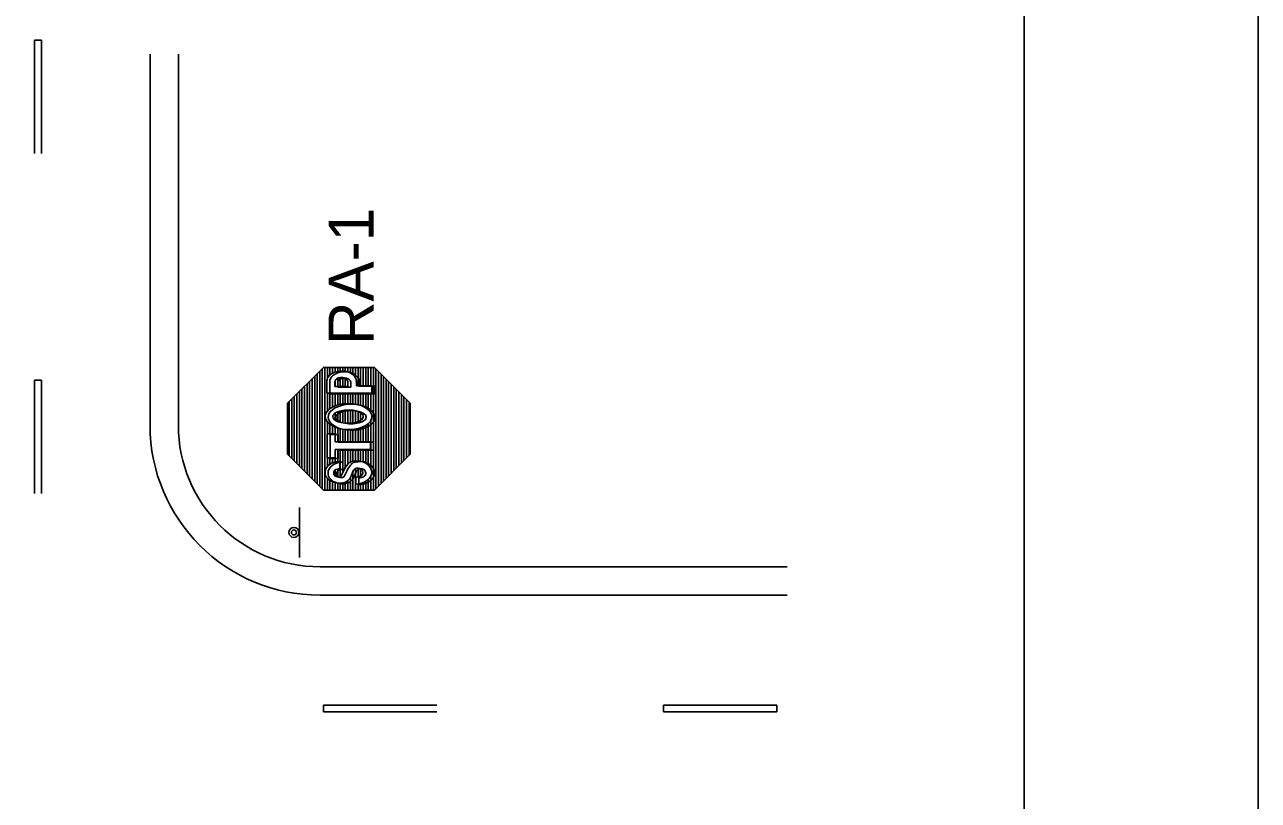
# Model space of a CAD drawing. Extents: x 1806 to 2022, y 110 to 389.
# Drawn here: x 1968.9 to 2021.6, y 280.3 to 313.4 of the extents above; entities that cross this region are included whole.
import ezdxf

# ---------------------------------------------------------------- set-up
doc = ezdxf.new("R2010")
doc.units = 0
for name, color, linetype in [('Level 10', 7, 'Continuous'), ('Level 2', 7, 'Continuous'), ('Level 44', 7, 'Continuous'), ('Level 50', 7, 'Continuous'), ('Level 60', 7, 'Continuous')]:
    doc.layers.add(name, color=color, linetype=linetype)

msp = doc.modelspace()

# ---------------------------------------------------------------- linework, layer by layer
at = {"layer": 'Level 10'}
for p, q in [((1974.267, 296.293), (1974.267, 312.134)), ((1975.477, 296.293), (1975.477, 312.134)), ((1981.525, 290.244), (2001.468, 290.244)), ((1981.525, 289.035), (2001.468, 289.035))]:
    msp.add_line(p, q, dxfattribs=at)
for radius in [7.258, 6.048]:
    msp.add_arc((1981.525, 296.293), radius, 180, 270, dxfattribs=at)
at = {"layer": 'Level 2'}
for p, q in [((1969.337, 312.722), (1969.337, 307.884)), ((1969.627, 312.722), (1969.337, 312.722)), ((1969.627, 307.884), (1969.627, 312.722)), ((1969.337, 298.208), (1969.337, 293.37)), ((1969.627, 298.208), (1969.337, 298.208)), ((1969.627, 293.37), (1969.627, 298.208)), ((1986.519, 284.342), (1981.681, 284.342)), ((1981.681, 284.342), (1981.681, 284.052)), ((1981.681, 284.052), (1986.519, 284.052)), ((2001.033, 284.342), (1996.195, 284.342)), ((1996.195, 284.342), (1996.195, 284.052)), ((1996.195, 284.052), (2001.033, 284.052)), ((2001.033, 284.052), (2001.033, 284.342))]:
    msp.add_line(p, q, dxfattribs=at)
at = {"layer": 'Level 44'}
for p, q in [((1981.668, 298.759), (1980.139, 297.23)), ((1983.845, 298.759), (1981.668, 298.759)), ((1985.375, 297.23), (1983.845, 298.759)), ((1981.815, 298.196), (1981.815, 297.662)), ((1981.943, 297.633), (1981.943, 298.169)), ((1982.16, 298.148), (1982.16, 297.939)), ((1982.16, 298.148), (1982.16, 297.939)), ((1982.718, 297.939), (1982.718, 298.144)), ((1982.718, 297.939), (1982.718, 298.144)), ((1983.078, 297.979), (1983.078, 298.179)), ((1983.201, 298.142), (1983.206, 297.951)), ((1983.206, 297.951), (1983.206, 298.151)), ((1981.815, 297.662), (1983.732, 297.662)), ((1983.859, 297.633), (1981.943, 297.633)), ((1982.16, 297.939), (1982.718, 297.939)), ((1982.16, 297.939), (1982.718, 297.939)), ((1982.287, 298.121), (1982.287, 297.913)), ((1982.287, 298.121), (1982.287, 297.913)), ((1982.287, 297.913), (1982.844, 297.913)), ((1982.287, 297.913), (1982.844, 297.913)), ((1982.844, 297.913), (1982.844, 298.117)), ((1982.844, 297.913), (1982.844, 298.117)), ((1983.732, 297.979), (1983.078, 297.979)), ((1983.206, 297.951), (1983.859, 297.951)), ((1983.732, 297.662), (1983.732, 297.979)), ((1983.859, 297.951), (1983.859, 297.633)), ((1980.139, 297.23), (1980.139, 295.052)), ((1985.375, 295.052), (1985.375, 297.23)), ((1981.876, 296.615), (1981.875, 296.625)), ((1982.202, 296.602), (1982.199, 296.615)), ((1982.177, 295.923), (1981.833, 295.923)), ((1981.833, 295.923), (1981.833, 294.904)), ((1981.961, 294.877), (1981.961, 295.897)), ((1981.961, 295.897), (1982.304, 295.897)), ((1982.177, 295.588), (1982.177, 295.923)), ((1983.676, 295.588), (1982.177, 295.588)), ((1982.304, 295.897), (1982.304, 295.561)), ((1982.304, 295.561), (1983.803, 295.561)), ((1983.676, 295.257), (1983.676, 295.588)), ((1983.803, 295.561), (1983.803, 295.229)), ((1980.139, 295.052), (1981.668, 293.523)), ((1982.168, 294.904), (1982.168, 295.257)), ((1982.168, 295.257), (1983.676, 295.257)), ((1983.803, 295.229), (1982.296, 295.229)), ((1982.296, 295.229), (1982.296, 294.877)), ((1983.845, 293.523), (1985.375, 295.052)), ((1981.833, 294.904), (1982.168, 294.904)), ((1982.296, 294.877), (1981.961, 294.877)), ((1982.369, 294.747), (1982.369, 294.421)), ((1982.496, 294.721), (1982.496, 294.393)), ((1983.057, 293.776), (1983.057, 294.076)), ((1983.184, 293.75), (1983.184, 294.05)), ((1981.668, 293.523), (1983.845, 293.523)), ((1983.563, 293.845), (1983.562, 293.843)), ((1980.65, 290.642), (1980.65, 292.775))]:
    msp.add_line(p, q, dxfattribs=at)
msp.add_lwpolyline([(1983.846, 298.759), (1985.375, 297.23), (1985.375, 295.052), (1983.846, 293.523), (1981.668, 293.523), (1980.14, 295.052), (1980.14, 297.23), (1981.668, 298.759)], close=True, dxfattribs=at)
for points in [[(1981.624, 293.567), (1981.624, 298.714)], [(1981.734, 293.523), (1981.734, 298.759)], [(1981.843, 298.295), (1981.843, 298.759)], [(1981.951, 298.436), (1981.951, 298.759)], [(1982.06, 298.505), (1982.06, 298.759)], [(1982.168, 298.557), (1982.168, 298.759)], [(1982.279, 298.583), (1982.279, 298.759)], [(1982.387, 298.598), (1982.387, 298.759)], [(1982.496, 298.601), (1982.496, 298.759)], [(1982.604, 298.587), (1982.604, 298.759)], [(1982.713, 298.557), (1982.713, 298.759)], [(1982.823, 298.519), (1982.823, 298.759)], [(1982.931, 298.445), (1982.931, 298.759)], [(1983.039, 298.295), (1983.039, 298.759)], [(1983.149, 297.979), (1983.149, 298.759)], [(1983.257, 297.979), (1983.257, 298.759)], [(1983.366, 297.979), (1983.366, 298.759)], [(1983.476, 297.979), (1983.476, 298.759)], [(1983.584, 297.979), (1983.584, 298.759)], [(1983.693, 297.979), (1983.693, 298.759)], [(1983.802, 293.523), (1983.802, 298.759)], [(1983.91, 293.589), (1983.91, 298.693)], [(1981.08, 294.111), (1981.08, 298.171)], [(1981.189, 294.003), (1981.189, 298.279)], [(1981.298, 293.894), (1981.298, 298.388)], [(1981.407, 293.785), (1981.407, 298.497)], [(1981.516, 293.677), (1981.516, 298.605)], [(1982.168, 297.939), (1982.168, 298.192)], [(1982.279, 297.939), (1982.279, 298.295)], [(1982.387, 297.939), (1982.387, 298.323)], [(1982.496, 297.934), (1982.496, 298.327)], [(1982.604, 297.939), (1982.604, 298.292)], [(1984.02, 293.698), (1984.02, 298.583)], [(1984.129, 293.806), (1984.129, 298.475)], [(1984.237, 293.915), (1984.237, 298.367)], [(1984.346, 294.025), (1984.346, 298.257)], [(1984.455, 294.134), (1984.455, 298.148)], [(1980.537, 294.656), (1980.537, 297.626)], [(1980.645, 294.548), (1980.645, 297.73)], [(1980.753, 294.439), (1980.753, 297.843)], [(1980.863, 294.331), (1980.863, 297.952)], [(1980.971, 294.22), (1980.971, 298.061)], [(1981.843, 296.889), (1981.843, 297.662)], [(1981.951, 296.995), (1981.951, 297.662)], [(1982.06, 297.064), (1982.06, 297.662)], [(1982.168, 297.111), (1982.168, 297.662)], [(1982.279, 297.151), (1982.279, 297.662)], [(1982.387, 297.178), (1982.387, 297.662)], [(1982.496, 297.199), (1982.496, 297.662)], [(1982.604, 297.208), (1982.604, 297.662)], [(1982.713, 297.217), (1982.713, 297.662)], [(1982.823, 297.212), (1982.823, 297.662)], [(1982.931, 297.205), (1982.931, 297.662)], [(1983.039, 297.187), (1983.039, 297.662)], [(1983.149, 297.165), (1983.149, 297.662)], [(1983.257, 297.133), (1983.257, 297.662)], [(1983.366, 297.089), (1983.366, 297.662)], [(1983.476, 297.033), (1983.476, 297.662)], [(1983.584, 296.955), (1983.584, 297.662)], [(1983.693, 296.824), (1983.693, 297.662)], [(1984.563, 294.242), (1984.563, 298.04)], [(1984.673, 294.351), (1984.673, 297.931)], [(1984.782, 294.461), (1984.782, 297.821)], [(1984.89, 294.569), (1984.89, 297.712)], [(1984.999, 294.677), (1984.999, 297.604)], [(1980.209, 294.983), (1980.209, 297.298)], [(1980.318, 294.873), (1980.318, 297.404)], [(1980.427, 294.764), (1980.427, 297.518)], [(1985.108, 294.787), (1985.108, 297.495)], [(1985.217, 294.901), (1985.217, 297.387)], [(1985.327, 295.004), (1985.327, 297.278)], [(1982.168, 296.503), (1982.168, 296.806)], [(1982.279, 296.45), (1982.279, 296.859)], [(1982.387, 296.42), (1982.387, 296.895)], [(1982.496, 296.39), (1982.496, 296.92)], [(1982.604, 296.384), (1982.604, 296.937)], [(1982.713, 296.377), (1982.713, 296.937)], [(1982.823, 296.377), (1982.823, 296.942)], [(1982.931, 296.39), (1982.931, 296.929)], [(1983.039, 296.411), (1983.039, 296.906)], [(1983.149, 296.445), (1983.149, 296.877)], [(1983.257, 296.494), (1983.257, 296.819)], [(1981.843, 295.923), (1981.843, 296.428)], [(1981.951, 295.923), (1981.951, 296.329)], [(1982.06, 295.923), (1982.06, 296.254)], [(1982.168, 295.923), (1982.168, 296.207)], [(1982.279, 295.588), (1982.279, 296.168)], [(1982.387, 295.588), (1982.387, 296.141)], [(1982.496, 295.588), (1982.496, 296.122)], [(1982.604, 295.592), (1982.604, 296.11)], [(1982.713, 295.588), (1982.713, 296.105)], [(1982.823, 295.588), (1982.823, 296.105)], [(1982.931, 295.588), (1982.931, 296.114)], [(1983.039, 295.588), (1983.039, 296.128)], [(1983.149, 295.588), (1983.149, 296.145)], [(1983.257, 295.588), (1983.257, 296.176)], [(1983.366, 295.588), (1983.366, 296.215)], [(1983.476, 295.588), (1983.476, 296.272)], [(1983.584, 295.588), (1983.584, 296.35)], [(1983.693, 294.447), (1983.693, 296.481)], [(1982.279, 294.742), (1982.279, 295.257)], [(1982.387, 294.103), (1982.387, 295.257)], [(1982.496, 294.242), (1982.496, 295.257)], [(1982.604, 294.487), (1982.604, 295.257)], [(1982.713, 294.634), (1982.713, 295.257)], [(1982.823, 294.717), (1982.823, 295.257)], [(1982.931, 294.747), (1982.931, 295.257)], [(1983.039, 294.764), (1983.039, 295.257)], [(1983.149, 294.764), (1983.149, 295.257)], [(1983.257, 294.757), (1983.257, 295.257)], [(1983.366, 294.722), (1983.366, 295.257)], [(1983.476, 294.669), (1983.476, 295.257)], [(1983.584, 294.591), (1983.584, 295.257)], [(1981.843, 294.53), (1981.843, 294.904)], [(1981.951, 294.626), (1981.951, 294.904)], [(1982.06, 294.686), (1982.06, 294.904)], [(1982.168, 294.717), (1982.168, 294.904)], [(1983.039, 293.523), (1983.039, 294.443)], [(1983.149, 294.086), (1983.149, 294.455)], [(1981.843, 293.523), (1981.843, 294.028)], [(1981.951, 293.523), (1981.951, 293.937)], [(1982.168, 294.134), (1982.168, 294.379)], [(1982.279, 294.086), (1982.279, 294.425)], [(1982.713, 293.523), (1982.713, 293.932)], [(1982.823, 293.523), (1982.823, 294.073)], [(1982.931, 293.523), (1982.931, 294.331)], [(1983.257, 294.119), (1983.257, 294.43)], [(1983.584, 293.523), (1983.584, 293.986)], [(1983.693, 293.523), (1983.693, 294.111)], [(1982.06, 293.523), (1982.06, 293.877)], [(1982.168, 293.523), (1982.168, 293.846)], [(1982.279, 293.523), (1982.279, 293.824)], [(1982.387, 293.523), (1982.387, 293.819)], [(1982.496, 293.523), (1982.496, 293.833)], [(1982.604, 293.523), (1982.604, 293.864)], [(1983.149, 293.523), (1983.149, 293.789)], [(1983.257, 293.523), (1983.257, 293.811)], [(1983.366, 293.523), (1983.366, 293.846)], [(1983.476, 293.523), (1983.476, 293.897)]]:
    msp.add_lwpolyline(points, dxfattribs=at)
for radius in [0.213, 0.107]:
    msp.add_circle((1980.411, 291.712), radius, dxfattribs=at)
for centre, radius, start, end in [((1982.131, 298.167), 0.318, 134.8528, 175.0441), ((1982.271, 298.068), 0.488, 119.2241, 138.5308), ((1982.271, 298.068), 0.488, 119.2241, 138.5308), ((1982.258, 298.141), 0.318, 134.8528, 175.0441), ((1982.318, 298.061), 0.519, 103.0674, 123.762), ((1982.398, 298.041), 0.488, 119.2241, 138.5308), ((1982.398, 298.041), 0.488, 119.2241, 138.5308), ((1982.341, 298.116), 0.189, 125.1198, 169.3117), ((1982.341, 298.116), 0.189, 125.1198, 169.3117), ((1982.445, 298.035), 0.519, 103.0674, 123.762), ((1982.471, 297.596), 1.008, 93.3903, 105.6597), ((1982.397, 298.028), 0.294, 98.6031, 124.217), ((1982.397, 298.028), 0.294, 98.6031, 124.217), ((1982.468, 298.089), 0.189, 125.1198, 169.3117), ((1982.468, 298.089), 0.189, 125.1198, 169.3117), ((1982.599, 297.569), 1.008, 93.3903, 105.6597), ((1982.435, 298.017), 0.312, 80.3416, 105.2342), ((1982.435, 298.017), 0.312, 80.3416, 105.2342), ((1982.524, 298.001), 0.294, 98.6031, 124.217), ((1982.524, 298.001), 0.294, 98.6031, 124.217), ((1982.452, 297.793), 0.81, 79.7521, 92.7916), ((1982.452, 297.793), 0.81, 79.7521, 92.7916), ((1982.562, 297.99), 0.312, 80.3417, 105.2342), ((1982.562, 297.99), 0.312, 80.3417, 105.2342), ((1982.473, 298.046), 0.278, 56.5085, 87.0313), ((1982.473, 298.046), 0.278, 56.5085, 87.0313), ((1982.579, 297.766), 0.81, 79.7521, 92.7916), ((1982.579, 297.766), 0.81, 79.7521, 92.7916), ((1982.389, 297.552), 1.058, 68.3153, 78.6698), ((1982.6, 298.02), 0.278, 56.5086, 87.0313), ((1982.6, 298.02), 0.278, 56.5086, 87.0313), ((1982.505, 298.1), 0.216, 11.9191, 55.7868), ((1982.505, 298.1), 0.216, 11.9191, 55.7868), ((1982.516, 297.525), 1.058, 68.3153, 78.6699), ((1982.632, 298.073), 0.216, 11.9191, 55.7868), ((1982.632, 298.073), 0.216, 11.9191, 55.7868), ((1982.591, 298.055), 0.516, 48.2922, 68.6031), ((1982.591, 298.055), 0.516, 48.2922, 68.6031), ((1982.718, 298.028), 0.516, 48.2922, 68.6031), ((1982.718, 298.028), 0.516, 48.2922, 68.6031), ((1982.739, 298.189), 0.319, 25.3838, 52.6187), ((1982.617, 298.094), 0.471, 16.602, 29.8091), ((1982.866, 298.162), 0.319, 25.3838, 52.6188), ((1982.965, 298.188), 0.111, 349.7909, 23.5419), ((1982.744, 298.067), 0.471, 16.602, 29.8091), ((1983.092, 298.162), 0.111, 349.7909, 23.5419), ((1982.095, 294.277), 0.355, 136.1369, 211.3987), ((1982.289, 294.129), 0.598, 104.564, 139.0063), ((1982.222, 294.25), 0.355, 136.1369, 211.3987), ((1982.416, 294.102), 0.599, 104.564, 139.0063), ((1982.384, 293.917), 0.829, 90.6952, 107.1451), ((1982.511, 293.89), 0.829, 90.6952, 107.1452), ((1983.28, 294.091), 0.783, 136.2465, 157.9263), ((1983.407, 294.064), 0.783, 136.2465, 157.9263), ((1981.847, 295.692), 1.368, 309.479, 313.426), ((1983.105, 293.95), 0.815, 95.9097, 111.9865), ((1981.974, 295.665), 1.369, 309.479, 313.4261), ((1983.232, 293.923), 0.815, 95.9097, 111.9865), ((1983.121, 294.242), 0.213, 82.5761, 120.4776), ((1983.102, 293.609), 1.154, 81.247, 93.9864), ((1983.229, 293.582), 1.154, 81.247, 93.9864), ((1983.147, 294.178), 0.275, 56.253, 88.7323), ((1983.022, 293.88), 0.907, 55.5092, 73.2894), ((1983.149, 293.853), 0.907, 55.5092, 73.2894), ((1983.237, 294.201), 0.521, 23.1413, 54.9905), ((1983.364, 294.174), 0.521, 23.1413, 54.9906), ((1982.277, 294.41), 0.58, 213.3662, 245.6734), ((1982.404, 294.383), 0.58, 213.3662, 245.6734), ((1982.296, 294.247), 0.184, 137.3017, 199.0119), ((1982.282, 294.261), 0.176, 203.8064, 262.2407), ((1982.329, 294.16), 0.27, 80.4412, 129.3244), ((1982.423, 294.22), 0.185, 137.3017, 199.0119), ((1982.409, 294.234), 0.176, 203.8064, 262.2407), ((1982.308, 294.24), 0.161, 254.131, 328.1476), ((1982.456, 294.133), 0.27, 80.4412, 129.3244), ((1982.435, 294.213), 0.161, 254.131, 328.1476), ((1981.495, 294.749), 1.12, 327.9816, 340.979), ((1982.391, 294.323), 0.508, 290.4481, 325.1107), ((1981.622, 294.722), 1.12, 327.9816, 340.979), ((1982.518, 294.296), 0.508, 290.4481, 325.1107), ((1979.489, 295.624), 3.68, 334.4624, 338.8312), ((1983.146, 294.235), 0.232, 124.2083, 164.1552), ((1979.616, 295.597), 3.681, 334.4624, 338.8312), ((1983.273, 294.208), 0.232, 124.2083, 164.1552), ((1983.062, 294.53), 0.457, 269.0171, 283.5172), ((1983.248, 294.215), 0.213, 82.5761, 120.4776), ((1983.148, 294.315), 0.229, 276.8728, 312.7449), ((1983.189, 294.503), 0.457, 269.0172, 283.5172), ((1983.274, 294.151), 0.275, 56.253, 88.7323), ((1983.145, 294.268), 0.207, 5.4374, 44.0625), ((1983.127, 294.284), 0.223, 320.6966, 1.4573), ((1983.275, 294.288), 0.229, 276.8728, 312.7449), ((1983.272, 294.241), 0.207, 5.4374, 44.0625), ((1983.254, 294.257), 0.223, 320.6966, 1.4573), ((1983.097, 294.499), 0.713, 298.4154, 323.6553), ((1983.224, 294.473), 0.713, 298.4154, 323.6553), ((1983.414, 294.277), 0.326, 322.0536, 22.7397), ((1983.541, 294.25), 0.326, 322.0536, 22.7397), ((1982.347, 294.633), 0.813, 247.7332, 267.1392), ((1982.474, 294.606), 0.813, 247.7332, 267.1392), ((1982.369, 294.533), 0.714, 264.8171, 285.9183), ((1982.496, 294.506), 0.714, 264.8171, 285.9183), ((1983.012, 294.778), 1.001, 272.3841, 294.9519), ((1983.14, 294.751), 1.001, 272.3841, 294.9519)]:
    msp.add_arc(centre, radius, start, end, dxfattribs=at)
for centre, major_axis, ratio, start_param, end_param in [((1982.746, 296.659), (0.998, -0.007), 0.558644, 3.185857, 9.451311), ((1982.873, 296.633), (0.998, -0.007), 0.558644, 0.656861, 3.168126), ((1982.873, 296.633), (0.998, -0.007), 0.558644, 3.185857, 4.129398), ((1982.723, 296.659), (0.652, 0.003), 0.432619, 3.239639, 9.473919), ((1982.85, 296.633), (0.652, 0.003), 0.432619, 0.881967, 3.190734), ((1982.85, 296.633), (0.652, 0.003), 0.432619, 3.239639, 3.888884), ((1982.873, 296.633), (0.998, -0.007), 0.558644, 4.129576, 6.939747), ((1982.85, 296.633), (0.652, 0.003), 0.432619, 3.890436, 7.165085)]:
    msp.add_ellipse(centre, major_axis=major_axis, ratio=ratio, start_param=start_param, end_param=end_param, dxfattribs=at)
at = {"layer": 'Level 60'}
for points in [[(1805.588, 389.179), (2021.588, 389.179), (2021.588, 110.179), (1805.588, 110.179)], [(1824.714, 378.37), (2011.588, 378.37), (2011.588, 120.988), (1824.714, 120.988)]]:
    msp.add_lwpolyline(points, close=True, dxfattribs=at)

# ---------------------------------------------------------------- texts
at = {"layer": 'Level 50'}
msp.add_text('RA-1', height=1.92, rotation=90, dxfattribs=at).set_placement((1983.812, 299.719))

doc.saveas('drawing.dxf')
